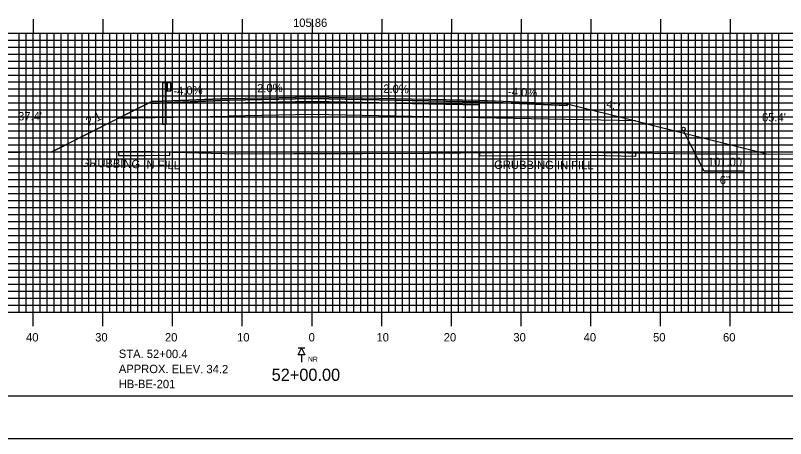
# Model space of a CAD drawing. Extents: x 1755888 to 1756232, y 442591 to 442811.
# Drawn here: x 1756011.5 to 1756122, y 442590.5 to 442651.2 of the extents above; entities that cross this region are included whole.
import ezdxf

# ---------------------------------------------------------------- set-up
doc = ezdxf.new("R2010")
doc.units = 0
for name, color, linetype in [('ANNOTATION', 7, 'Continuous'), ('BORDER', 7, 'Continuous'), ('BORING - NO REFUSAL', 7, 'Continuous'), ('D_Guardrail_Beam_Lt', 7, 'Continuous'), ('D_Roadway_Centerline', 7, 'Continuous'), ('D_Roadway_Centerline_Text', 7, 'Continuous'), ('D_Roadway_Edge_Shoulder', 7, 'Continuous'), ('D_Roadway_Edge_TW', 7, 'Continuous'), ('D_Roadway_Pavement', 7, 'Continuous'), ('D_Roadway_SlopeLines', 7, 'Continuous'), ('D_Roadway_SubGrade', 7, 'Continuous'), ('D_Text_Standard', 7, 'Continuous'), ('DIMENSIONS', 7, 'Continuous'), ('GRUBBING IN FILL', 7, 'Continuous'), ('H_V ANNOTATION', 7, 'Continuous'), ('MAJOR', 7, 'Continuous'), ('MINOR', 7, 'Continuous'), ('PDRAIN', 7, 'Continuous'), ('PLOT BOUNDARY', 7, 'Continuous'), ('S_Roadway_Centerline', 7, 'Continuous')]:
    doc.layers.add(name, color=color, linetype=linetype)

msp = doc.modelspace()

# ---------------------------------------------------------------- linework, layer by layer
at = {"layer": 'ANNOTATION'}
msp.add_lwpolyline([(1756116.01, 442628.89), (1756110.32, 442628.89), (1756107.36, 442634.67)], dxfattribs=at)
at = {"layer": 'BORDER'}
msp.add_lwpolyline([(1755904.46, 442596.67), (1756224.46, 442596.67), (1756224.46, 442806.67), (1755904.46, 442806.67)], close=True, dxfattribs=at)
at = {"layer": 'BORING - NO REFUSAL'}
for p, q in [((1756053.04, 442603.5), (1756052.08, 442603.5)), ((1756052.56, 442602.54), (1756052.56, 442601.48))]:
    msp.add_line(p, q, dxfattribs=at)
msp.add_lwpolyline([(1756052.56, 442603.5), (1756053.04, 442602.54), (1756052.08, 442602.54)], close=True, dxfattribs=at)
at = {"layer": 'D_Guardrail_Beam_Lt'}
for p, q in [((1756032.63, 442641.55), (1756032.63, 442635.55)), ((1756033.1, 442641.55), (1756032.63, 442641.55)), ((1756033.79, 442641.55), (1756033.1, 442641.55)), ((1756033.1, 442641.55), (1756033.1, 442640.38)), ((1756033.16, 442641.55), (1756033.16, 442640.38)), ((1756033.27, 442641.55), (1756033.27, 442640.38)), ((1756033.79, 442640.38), (1756033.79, 442641.55)), ((1756033.79, 442641.47), (1756033.86, 442641.45)), ((1756033.88, 442641.45), (1756034.02, 442641.35)), ((1756033.1, 442640.38), (1756033.79, 442640.38)), ((1756033.12, 442635.55), (1756033.12, 442640.38)), ((1756033.79, 442641), (1756033.79, 442640.93)), ((1756033.86, 442640.48), (1756033.79, 442640.47)), ((1756034.02, 442641.2), (1756033.82, 442641.07)), ((1756033.82, 442640.87), (1756034.02, 442640.73)), ((1756034.02, 442640.59), (1756033.88, 442640.49)), ((1756033.12, 442635.55), (1756032.63, 442635.55))]:
    msp.add_line(p, q, dxfattribs=at)
for centre, major_axis, start_param, end_param in [((1756033.85, 442641.41), (0.0417, 0), 0.959931, 1.376053), ((1756033.87, 442641), (-0.0789, 0), 5.323254, 6.283185), ((1756033.87, 442640.93), (-0.0789, 0), 6.283185, 7.243116), ((1756033.85, 442640.52), (0.0417, 0), 4.907132, 5.323254), ((1756033.97, 442641.28), (0.0877, 0), 5.323254, 7.243116), ((1756033.97, 442640.66), (0.0877, 0), 5.323254, 7.243116)]:
    msp.add_ellipse(centre, major_axis=major_axis, ratio=0.995501, start_param=start_param, end_param=end_param, dxfattribs=at)
at = {"layer": 'D_Roadway_Centerline'}
msp.add_lwpolyline([(1756016.63, 442631.63), (1756026.31, 442636.47), (1756031.06, 442638.85), (1756034.06, 442638.97), (1756042.06, 442639.29), (1756054.06, 442639.53), (1756066.06, 442639.29), (1756078.06, 442639.05), (1756090.69, 442638.54), (1756100.46, 442636.1), (1756102.69, 442635.54), (1756119.51, 442631.34)], dxfattribs=at)
at = {"layer": 'D_Roadway_Edge_Shoulder'}
for points in [[(1756042.06, 442639.29), (1756034.06, 442638.97), (1756034.06, 442638.97), (1756031.06, 442638.85), (1756031.06, 442638.6), (1756042.06, 442639.04)], [(1756078.06, 442639.05), (1756090.69, 442638.54), (1756090.69, 442638.29), (1756078.06, 442638.8)]]:
    msp.add_lwpolyline(points, close=True, dxfattribs=at)
at = {"layer": 'D_Roadway_Edge_TW'}
for points in [[(1756042.06, 442639.04), (1756042.06, 442639.29), (1756054.06, 442639.53), (1756066.06, 442639.29), (1756066.06, 442639.04), (1756054.06, 442639.28)], [(1756066.06, 442639.29), (1756078.06, 442639.05), (1756078.06, 442638.8), (1756066.06, 442639.04)]]:
    msp.add_lwpolyline(points, close=True, dxfattribs=at)
at = {"layer": 'D_Roadway_Pavement'}
for points in [[(1756042.06, 442638.62), (1756042.06, 442639.04), (1756054.06, 442639.28), (1756066.06, 442639.04), (1756066.06, 442638.62), (1756054.06, 442638.86)], [(1756066.06, 442639.04), (1756078.06, 442638.8), (1756078.06, 442638.38), (1756066.06, 442638.62)]]:
    msp.add_lwpolyline(points, close=True, dxfattribs=at)
for points in [[(1756042.06, 442639.04), (1756042.06, 442638.62)], [(1756078.06, 442638.8), (1756078.06, 442638.38)], [(1756078.06, 442638.8), (1756078.06, 442638.38)], [(1756078.06, 442638.8), (1756078.06, 442638.38)]]:
    msp.add_lwpolyline(points, dxfattribs=at)
at = {"layer": 'D_Roadway_SlopeLines'}
msp.add_lwpolyline([(1756031.06, 442638.85), (1756016.63, 442631.63)], dxfattribs=at)
at = {"layer": 'D_Roadway_SubGrade'}
for points in [[(1756042.06, 442638.62), (1756042.06, 442639.04), (1756031.06, 442638.6), (1756031.06, 442638.85), (1756026.31, 442636.47), (1756042.06, 442636.79)], [(1756042.06, 442636.79), (1756042.06, 442638.62), (1756054.06, 442638.86), (1756066.06, 442638.62), (1756066.06, 442636.79), (1756054.06, 442637.03)], [(1756066.06, 442638.62), (1756078.06, 442638.38), (1756078.06, 442636.55), (1756066.06, 442636.79)], [(1756078.06, 442638.38), (1756078.06, 442638.8), (1756090.69, 442638.29), (1756090.69, 442638.54), (1756100.46, 442636.1), (1756078.06, 442636.55)]]:
    msp.add_lwpolyline(points, close=True, dxfattribs=at)
at = {"layer": 'DIMENSIONS'}
msp.add_line((1756102.69, 442635.54), (1756106.69, 442634.54), dxfattribs=at)
at = {"layer": 'GRUBBING IN FILL'}
for p, q in [((1756026.31, 442631.65), (1756026.31, 442631.15)), ((1756100.46, 442631.51), (1756100.46, 442631.01))]:
    msp.add_line(p, q, dxfattribs=at)
for points in [[(1756026.31, 442631.15), (1756028.59, 442631.15), (1756029.95, 442631.15), (1756031.35, 442631.17), (1756033.64, 442631.12), (1756033.64, 442631.62), (1756031.35, 442631.67), (1756029.1, 442631.65), (1756026.31, 442631.65)], [(1756026.31, 442631.15), (1756028.59, 442631.15), (1756029.95, 442631.15), (1756031.35, 442631.17), (1756033.64, 442631.12), (1756033.64, 442631.62), (1756031.35, 442631.67), (1756029.1, 442631.65), (1756026.31, 442631.65)], [(1756078.13, 442631.55), (1756084.66, 442631.61), (1756090.51, 442631.63), (1756097.55, 442631.54), (1756100.46, 442631.51), (1756100.46, 442631.01), (1756096.28, 442631.06), (1756088.93, 442631.15), (1756078.13, 442631.05)], [(1756078.13, 442631.55), (1756084.66, 442631.61), (1756090.51, 442631.63), (1756097.55, 442631.54), (1756100.46, 442631.51), (1756100.46, 442631.01), (1756096.28, 442631.06), (1756088.93, 442631.15), (1756078.13, 442631.05)]]:
    msp.add_lwpolyline(points, close=True, dxfattribs=at)
at = {"layer": 'MAJOR'}
for p, q in [((1756014.06, 442650.67), (1756014.06, 442648.67)), ((1756024.06, 442650.67), (1756024.06, 442648.67)), ((1756034.06, 442650.67), (1756034.06, 442648.67)), ((1756044.06, 442650.67), (1756044.06, 442648.67)), ((1756054.06, 442650.67), (1756054.06, 442648.67)), ((1756064.06, 442650.67), (1756064.06, 442648.67)), ((1756074.06, 442650.67), (1756074.06, 442648.67)), ((1756084.06, 442650.67), (1756084.06, 442648.67)), ((1756094.06, 442650.67), (1756094.06, 442648.67)), ((1756104.06, 442650.67), (1756104.06, 442648.67)), ((1756114.06, 442650.67), (1756114.06, 442648.67)), ((1755914.06, 442648.67), (1756194.06, 442648.67)), ((1755914.06, 442648.67), (1756194.06, 442648.67)), ((1756014.06, 442608.67), (1756014.06, 442648.67)), ((1756024.06, 442608.67), (1756024.06, 442648.67)), ((1756034.06, 442608.67), (1756034.06, 442648.67)), ((1756044.06, 442608.67), (1756044.06, 442648.67)), ((1756054.06, 442608.67), (1756054.06, 442648.67)), ((1756064.06, 442608.67), (1756064.06, 442648.67)), ((1756074.06, 442608.67), (1756074.06, 442648.67)), ((1756084.06, 442608.67), (1756084.06, 442648.67)), ((1756094.06, 442608.67), (1756094.06, 442648.67)), ((1756104.06, 442608.67), (1756104.06, 442648.67)), ((1756114.06, 442608.67), (1756114.06, 442648.67)), ((1755914.06, 442643.67), (1756194.06, 442643.67)), ((1755914.06, 442638.67), (1756194.06, 442638.67)), ((1755914.06, 442633.67), (1756194.06, 442633.67)), ((1755914.06, 442628.67), (1756194.06, 442628.67)), ((1755914.06, 442623.67), (1756194.06, 442623.67)), ((1755914.06, 442618.67), (1756194.06, 442618.67)), ((1755914.06, 442613.67), (1756194.06, 442613.67)), ((1755914.06, 442608.67), (1756194.06, 442608.67)), ((1755914.06, 442608.67), (1756194.06, 442608.67)), ((1756014.06, 442606.66), (1756014.06, 442608.67)), ((1756024.06, 442606.66), (1756024.06, 442608.67)), ((1756034.06, 442606.66), (1756034.06, 442608.67)), ((1756044.06, 442606.66), (1756044.06, 442608.67)), ((1756054.06, 442606.66), (1756054.06, 442608.67)), ((1756064.06, 442606.66), (1756064.06, 442608.67)), ((1756074.06, 442606.66), (1756074.06, 442608.67)), ((1756084.06, 442606.66), (1756084.06, 442608.67)), ((1756094.06, 442606.66), (1756094.06, 442608.67)), ((1756104.06, 442606.66), (1756104.06, 442608.67)), ((1756114.06, 442606.66), (1756114.06, 442608.67))]:
    msp.add_line(p, q, dxfattribs=at)
at = {"layer": 'MINOR'}
for p, q in [((1756012.06, 442608.67), (1756012.06, 442648.67)), ((1756013.06, 442608.67), (1756013.06, 442648.67)), ((1756015.06, 442608.67), (1756015.06, 442648.67)), ((1756016.06, 442608.67), (1756016.06, 442648.67)), ((1756017.06, 442608.67), (1756017.06, 442648.67)), ((1756018.06, 442608.67), (1756018.06, 442648.67)), ((1756019.06, 442608.67), (1756019.06, 442648.67)), ((1756020.06, 442608.67), (1756020.06, 442648.67)), ((1756021.06, 442608.67), (1756021.06, 442648.67)), ((1756022.06, 442608.67), (1756022.06, 442648.67)), ((1756023.06, 442608.67), (1756023.06, 442648.67)), ((1756025.06, 442608.67), (1756025.06, 442648.67)), ((1756026.06, 442608.67), (1756026.06, 442648.67)), ((1756027.06, 442608.67), (1756027.06, 442648.67)), ((1756028.06, 442608.67), (1756028.06, 442648.67)), ((1756029.06, 442608.67), (1756029.06, 442648.67)), ((1756030.06, 442608.67), (1756030.06, 442648.67)), ((1756031.06, 442608.67), (1756031.06, 442648.67)), ((1756032.06, 442608.67), (1756032.06, 442648.67)), ((1756033.06, 442608.67), (1756033.06, 442648.67)), ((1756035.06, 442608.67), (1756035.06, 442648.67)), ((1756036.06, 442608.67), (1756036.06, 442648.67)), ((1756037.06, 442608.67), (1756037.06, 442648.67)), ((1756038.06, 442608.67), (1756038.06, 442648.67)), ((1756039.06, 442608.67), (1756039.06, 442648.67)), ((1756040.06, 442608.67), (1756040.06, 442648.67)), ((1756041.06, 442608.67), (1756041.06, 442648.67)), ((1756042.06, 442608.67), (1756042.06, 442648.67)), ((1756043.06, 442608.67), (1756043.06, 442648.67)), ((1756045.06, 442608.67), (1756045.06, 442648.67)), ((1756046.06, 442608.67), (1756046.06, 442648.67)), ((1756047.06, 442608.67), (1756047.06, 442648.67)), ((1756048.06, 442608.67), (1756048.06, 442648.67)), ((1756049.06, 442608.67), (1756049.06, 442648.67)), ((1756050.06, 442608.67), (1756050.06, 442648.67)), ((1756051.06, 442608.67), (1756051.06, 442648.67)), ((1756052.06, 442608.67), (1756052.06, 442648.67)), ((1756053.06, 442608.67), (1756053.06, 442648.67)), ((1756055.06, 442608.67), (1756055.06, 442648.67)), ((1756056.06, 442608.67), (1756056.06, 442648.67)), ((1756057.06, 442608.67), (1756057.06, 442648.67)), ((1756058.06, 442608.67), (1756058.06, 442648.67)), ((1756059.06, 442608.67), (1756059.06, 442648.67)), ((1756060.06, 442608.67), (1756060.06, 442648.67)), ((1756061.06, 442608.67), (1756061.06, 442648.67)), ((1756062.06, 442608.67), (1756062.06, 442648.67)), ((1756063.06, 442608.67), (1756063.06, 442648.67)), ((1756065.06, 442608.67), (1756065.06, 442648.67)), ((1756066.06, 442608.67), (1756066.06, 442648.67)), ((1756067.06, 442608.67), (1756067.06, 442648.67)), ((1756068.06, 442608.67), (1756068.06, 442648.67)), ((1756069.06, 442608.67), (1756069.06, 442648.67)), ((1756070.06, 442608.67), (1756070.06, 442648.67)), ((1756071.06, 442608.67), (1756071.06, 442648.67)), ((1756072.06, 442608.67), (1756072.06, 442648.67)), ((1756073.06, 442608.67), (1756073.06, 442648.67)), ((1756075.06, 442608.67), (1756075.06, 442648.67)), ((1756076.06, 442608.67), (1756076.06, 442648.67)), ((1756077.06, 442608.67), (1756077.06, 442648.67)), ((1756078.06, 442608.67), (1756078.06, 442648.67)), ((1756079.06, 442608.67), (1756079.06, 442648.67)), ((1756080.06, 442608.67), (1756080.06, 442648.67)), ((1756081.06, 442608.67), (1756081.06, 442648.67)), ((1756082.06, 442608.67), (1756082.06, 442648.67)), ((1756083.06, 442608.67), (1756083.06, 442648.67)), ((1756085.06, 442608.67), (1756085.06, 442648.67)), ((1756086.06, 442608.67), (1756086.06, 442648.67)), ((1756087.06, 442608.67), (1756087.06, 442648.67)), ((1756088.06, 442608.67), (1756088.06, 442648.67)), ((1756089.06, 442608.67), (1756089.06, 442648.67)), ((1756090.06, 442608.67), (1756090.06, 442648.67)), ((1756091.06, 442608.67), (1756091.06, 442648.67)), ((1756092.06, 442608.67), (1756092.06, 442648.67)), ((1756093.06, 442608.67), (1756093.06, 442648.67)), ((1756095.06, 442608.67), (1756095.06, 442648.67)), ((1756096.06, 442608.67), (1756096.06, 442648.67)), ((1756097.06, 442608.67), (1756097.06, 442648.67)), ((1756098.06, 442608.67), (1756098.06, 442648.67)), ((1756099.06, 442608.67), (1756099.06, 442648.67)), ((1756100.06, 442608.67), (1756100.06, 442648.67)), ((1756101.06, 442608.67), (1756101.06, 442648.67)), ((1756102.06, 442608.67), (1756102.06, 442648.67)), ((1756103.06, 442608.67), (1756103.06, 442648.67)), ((1756105.06, 442608.67), (1756105.06, 442648.67)), ((1756106.06, 442608.67), (1756106.06, 442648.67)), ((1756107.06, 442608.67), (1756107.06, 442648.67)), ((1756108.06, 442608.67), (1756108.06, 442648.67)), ((1756109.06, 442608.67), (1756109.06, 442648.67)), ((1756110.06, 442608.67), (1756110.06, 442648.67)), ((1756111.06, 442608.67), (1756111.06, 442648.67)), ((1756112.06, 442608.67), (1756112.06, 442648.67)), ((1756113.06, 442608.67), (1756113.06, 442648.67)), ((1756115.06, 442608.67), (1756115.06, 442648.67)), ((1756116.06, 442608.67), (1756116.06, 442648.67)), ((1756117.06, 442608.67), (1756117.06, 442648.67)), ((1756118.06, 442608.67), (1756118.06, 442648.67)), ((1756119.06, 442608.67), (1756119.06, 442648.67)), ((1756120.06, 442608.67), (1756120.06, 442648.67)), ((1756121.06, 442608.67), (1756121.06, 442648.67)), ((1755914.06, 442647.67), (1756194.06, 442647.67)), ((1755914.06, 442646.67), (1756194.06, 442646.67)), ((1755914.06, 442645.67), (1756194.06, 442645.67)), ((1755914.06, 442644.67), (1756194.06, 442644.67)), ((1755914.06, 442642.67), (1756194.06, 442642.67)), ((1755914.06, 442641.67), (1756194.06, 442641.67)), ((1755914.06, 442640.67), (1756194.06, 442640.67)), ((1755914.06, 442639.67), (1756194.06, 442639.67)), ((1755914.06, 442637.67), (1756194.06, 442637.67)), ((1755914.06, 442636.67), (1756194.06, 442636.67)), ((1755914.06, 442635.67), (1756194.06, 442635.67)), ((1755914.06, 442634.67), (1756194.06, 442634.67)), ((1755914.06, 442632.67), (1756194.06, 442632.67)), ((1755914.06, 442631.67), (1756194.06, 442631.67)), ((1755914.06, 442630.67), (1756194.06, 442630.67)), ((1755914.06, 442629.67), (1756194.06, 442629.67)), ((1755914.06, 442627.67), (1756194.06, 442627.67)), ((1755914.06, 442626.67), (1756194.06, 442626.67)), ((1755914.06, 442625.67), (1756194.06, 442625.67)), ((1755914.06, 442624.67), (1756194.06, 442624.67)), ((1755914.06, 442622.67), (1756194.06, 442622.67)), ((1755914.06, 442621.67), (1756194.06, 442621.67)), ((1755914.06, 442620.67), (1756194.06, 442620.67)), ((1755914.06, 442619.67), (1756194.06, 442619.67)), ((1755914.06, 442617.67), (1756194.06, 442617.67)), ((1755914.06, 442616.67), (1756194.06, 442616.67)), ((1755914.06, 442615.67), (1756194.06, 442615.67)), ((1755914.06, 442614.67), (1756194.06, 442614.67)), ((1755914.06, 442612.67), (1756194.06, 442612.67)), ((1755914.06, 442611.67), (1756194.06, 442611.67)), ((1755914.06, 442610.67), (1756194.06, 442610.67)), ((1755914.06, 442609.67), (1756194.06, 442609.67))]:
    msp.add_line(p, q, dxfattribs=at)
at = {"layer": 'PDRAIN'}
msp.add_circle((1756107.36, 442634.92), 0.25, dxfattribs=at)
at = {"layer": 'PLOT BOUNDARY'}
msp.add_lwpolyline([(1755888.27, 442590.55), (1756228.27, 442590.55), (1756228.27, 442810.55), (1755888.27, 442810.55)], close=True, dxfattribs=at)
at = {"layer": 'S_Roadway_Centerline'}
msp.add_lwpolyline([(1755998.58, 442631.59), (1756012.24, 442631.63), (1756029.98, 442631.65), (1756031.35, 442631.67), (1756032.22, 442631.65), (1756043.38, 442631.39), (1756051.43, 442631.43), (1756055.29, 442631.43), (1756061.31, 442631.44), (1756070.75, 442631.47), (1756084.66, 442631.61), (1756088.93, 442631.65), (1756092.1, 442631.61), (1756103, 442631.47), (1756109.15, 442631.36), (1756114.89, 442631.37), (1756125.04, 442631.3)], dxfattribs=at)

# ---------------------------------------------------------------- texts
at = {"layer": 'ANNOTATION'}
for s, rotation, p in [('-4.0%', 2.2906, (1756034.19, 442639.77)), ('-2.0%', 1.1458, (1756045.66, 442640.16)), ('-2.0%', 358.8542, (1756063.74, 442640.13)), ('-4.0%', 357.7094, (1756082.16, 442639.69)), ('4:1', 345.9638, (1756096.2, 442638.03)), ('2:1', 26.5651, (1756021.99, 442635.35))]:
    msp.add_text(s, height=1.2, rotation=rotation, dxfattribs=at).set_placement(p)
for s, p in [('101.00', (1756110.85, 442629.61)), ('6"', (1756112.56, 442627.01))]:
    msp.add_text(s, height=1.2, dxfattribs=at).set_placement(p)
at = {"layer": 'BORING - NO REFUSAL'}
for s, p in [('STA. 52+00.4', (1756026.34, 442602.11)), ('APPROX. ELEV. 34.2', (1756026.34, 442599.95)), ('HB-BE-201', (1756026.33, 442597.79))]:
    msp.add_text(s, height=1.2, rotation=359.8142, dxfattribs=at).set_placement(p)
msp.add_text('NR', height=0.7, dxfattribs=at).set_placement((1756053.49, 442601.58))
at = {"layer": 'D_Roadway_Centerline'}
for s, p in [('C', (1756054.05, 442639.53)), ('L', (1756054.06, 442639.52))]:
    msp.add_text(s, height=0.0146, dxfattribs=at).set_placement(p)
at = {"layer": 'D_Roadway_Centerline_Text'}
msp.add_text('105.86', height=1.2, dxfattribs=at).set_placement((1756051.34, 442649.56))
at = {"layer": 'D_Text_Standard'}
for s, p in [("37.4'", (1756011.89, 442636.16)), ("65.4'", (1756118.61, 442636.01))]:
    msp.add_text(s, height=1.2, dxfattribs=at).set_placement(p)
at = {"layer": 'GRUBBING IN FILL'}
for rotation, p in [(358.498, (1756020.84, 442629.51)), (359.7271, (1756080.19, 442629.21))]:
    msp.add_text('GRUBBING IN FILL', height=1.2, rotation=rotation, dxfattribs=at).set_placement(p)
at = {"layer": 'H_V ANNOTATION'}
for s, height, p in [('40', 1.2, (1756013.03, 442604.47)), ('30', 1.2, (1756022.95, 442604.47)), ('20', 1.2, (1756032.96, 442604.47)), ('10', 1.2, (1756043.31, 442604.47)), ('0', 1.2, (1756053.57, 442604.47)), ('10', 1.2, (1756063.31, 442604.47)), ('20', 1.2, (1756072.96, 442604.47)), ('30', 1.2, (1756082.95, 442604.47)), ('40', 1.2, (1756093.03, 442604.47)), ('50', 1.2, (1756102.99, 442604.47)), ('60', 1.2, (1756113.03, 442604.47)), ('52+00.00', 1.75, (1756048.27, 442598.82))]:
    msp.add_text(s, height=height, dxfattribs=at).set_placement(p)

doc.saveas('drawing.dxf')
